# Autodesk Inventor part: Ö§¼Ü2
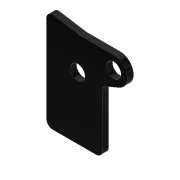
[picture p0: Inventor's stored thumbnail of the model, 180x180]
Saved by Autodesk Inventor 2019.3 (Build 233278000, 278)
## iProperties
Created: 2017-10
Part Number: Ö§¼Ü2
Material: Ogólny
Document SubType Name: Modeling
Designer: CADENGINEERING4
Density: 1 g/cm^3
Appearance: Gładki — czarny
Author: CADENGINEERING4
Revision Number: ÈÎºÎ
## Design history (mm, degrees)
feature "ÇÐ³ý-À­Éì3"
node "Bryła1"
